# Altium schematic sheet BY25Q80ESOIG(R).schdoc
size 127 x 101 mm
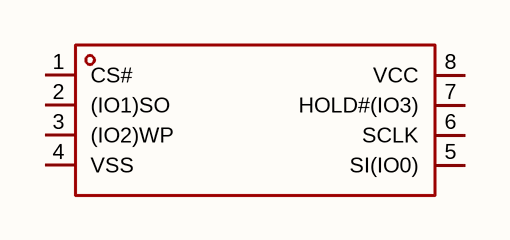
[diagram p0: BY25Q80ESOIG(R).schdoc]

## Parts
U?  by25q80esoig(r)  [TSSOP-8_L4.4-W3.0-P0.65-LS6.4-BL]  (value not drawn)

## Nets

Not connected (* = marked no-connect by the designer): U? 1(CS#) 2((IO1)SO) 3((IO2)WP) 4(VSS) 5(SI(IO0)) 6(SCLK) 7(HOLD#(IO3)) 8(VCC)

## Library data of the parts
U? = by25q80esoig(r): 接口类型:SPI;存储容量:8Mbit;时钟频率(fc):120MHz;; Manufacturer: BOYAMICRO(博雅); AddInBom: yes; ModelId: 85577802f9634e7e85ffa2fd25a37b6f; ModelName: TSSOP-8_L4.4-W3.0-P0.65-LS6.4-BL-2; ModelTransform: 118.11,251.968,0,0,0,0,0,0,0; Interface: SPI; Memory Size: 8Mbit; Clock Frequency: 120MHz; Voltage - Supply: 2.7V~3.6V; Standby Supply Current: 5uA; Program / Erase Cycles: 100000次; Page Programming Time (Tpp): 400us; Block Erase Time(tBE): 150ms@(64KB); Data Retention - TDR (Year): 20年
